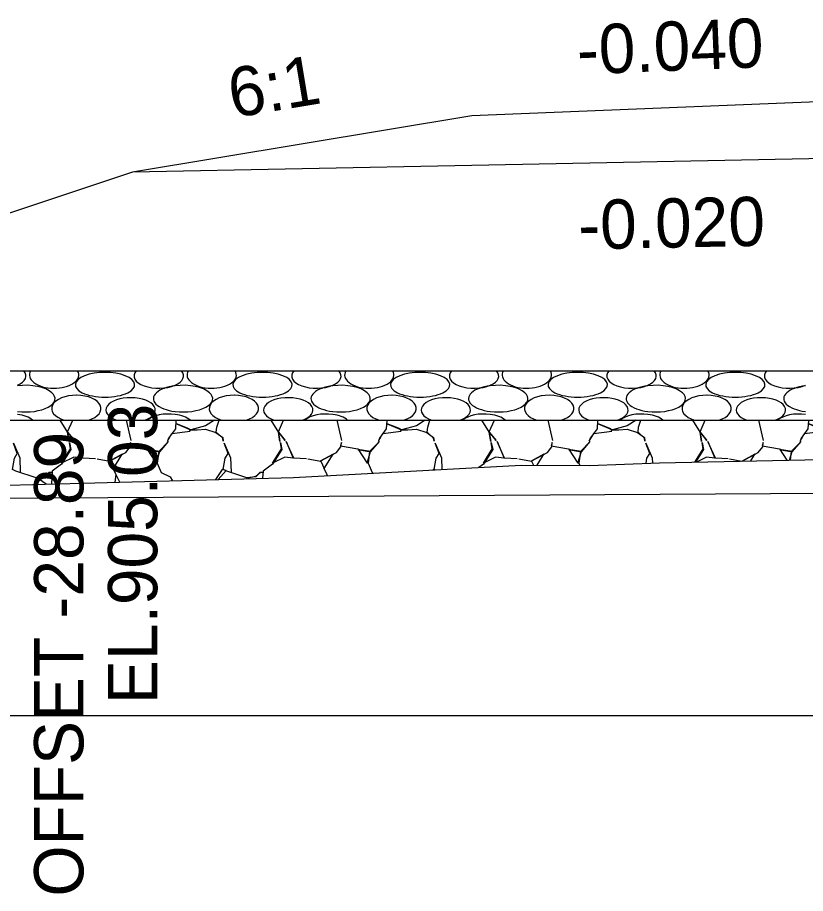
# Model space of a CAD drawing. Extents: x -26 to 4781, y -31 to 24738.
# Drawn here: x 2268.78 to 2284.77, y 13996.39 to 14014.17 of the extents above; entities that cross this region are included whole.
import ezdxf

# ---------------------------------------------------------------- set-up
doc = ezdxf.new("R2010")
doc.units = 0
for name, color, linetype in [('DESIGN - SCRATCH - User 1', 7, 'Continuous'), ('DESIGN - SHEET - Light Grid', 7, 'Continuous'), ('DESIGN - TRANSPORTATION - Proposed Layout Patterning', 7, 'Continuous'), ('DESIGN - TYPICAL - Finished Grade and Subgrade', 7, 'Continuous'), ('DESIGN - TYPICAL - Finished Grade Slopes Text', 7, 'Continuous'), ('DESIGN - TYPICAL - Subgrade Cross Slope Text', 7, 'Continuous'), ('DESIGN - TYPICAL - Subgrade Tie Text', 7, 'Continuous'), ('GEOTECHNICAL – SCRATCH – Level 1', 7, 'Continuous'), ('SURVEY - GROUND - Top of Ground', 7, 'Continuous')]:
    doc.layers.add(name, color=color, linetype=linetype)

msp = doc.modelspace()

# ---------------------------------------------------------------- linework, layer by layer
at = {"layer": 'DESIGN - SCRATCH - User 1'}
for p in [(2365.227, 14005), (2320.053, 14004.723)]:
    msp.add_line(p, (2250.908, 14004.298), dxfattribs=at)
at = {"layer": 'DESIGN - SHEET - Light Grid'}
msp.add_line((2000, 14000), (2300, 14000), dxfattribs=at)
at = {"layer": 'DESIGN - TRANSPORTATION - Proposed Layout Patterning'}
for p, q in [((2271.083, 14005.585), (2270.988, 14006)), ((2275.363, 14005.585), (2275.268, 14006)), ((2279.643, 14005.585), (2279.548, 14006)), ((2283.923, 14005.585), (2283.828, 14005.999)), ((2283.233, 14005.215), (2283.479, 14005.168))]:
    msp.add_line(p, q, dxfattribs=at)
for points in [[(2269.637, 14006), (2269.793, 14005.745), (2269.823, 14005.565), (2269.793, 14005.755), (2269.933, 14005.585), (2269.793, 14005.765), (2269.899, 14006)], [(2271.991, 14006), (2271.993, 14005.995), (2271.983, 14005.825), (2271.843, 14005.635), (2271.823, 14005.575), (2271.913, 14005.725), (2272.283, 14005.775), (2272.263, 14005.825), (2272.003, 14005.925), (2272.293, 14005.805), (2272.423, 14005.805), (2272.593, 14005.815), (2272.803, 14005.745), (2272.943, 14005.645), (2272.953, 14005.575), (2272.943, 14005.635), (2272.813, 14005.755), (2272.823, 14005.855), (2272.869, 14006)], [(2272.773, 14006), (2272.593, 14005.885), (2272.293, 14005.805)], [(2273.917, 14006), (2274.073, 14005.745), (2274.103, 14005.565), (2274.073, 14005.755), (2274.213, 14005.585), (2274.073, 14005.765), (2274.179, 14006)], [(2276.271, 14006), (2276.273, 14005.995), (2276.263, 14005.825), (2276.123, 14005.635), (2276.103, 14005.575), (2276.193, 14005.725), (2276.563, 14005.775), (2276.543, 14005.825), (2276.283, 14005.925), (2276.573, 14005.805), (2276.703, 14005.805), (2276.873, 14005.815), (2277.083, 14005.745), (2277.223, 14005.645), (2277.233, 14005.575), (2277.223, 14005.635), (2277.093, 14005.755), (2277.103, 14005.855), (2277.148, 14006)], [(2277.053, 14006), (2276.873, 14005.885), (2276.573, 14005.805)], [(2278.197, 14006), (2278.353, 14005.745), (2278.383, 14005.565), (2278.353, 14005.755), (2278.493, 14005.585), (2278.353, 14005.765), (2278.459, 14006)], [(2280.551, 14005.999), (2280.553, 14005.995), (2280.543, 14005.825), (2280.403, 14005.635), (2280.383, 14005.575), (2280.473, 14005.725), (2280.843, 14005.775), (2280.823, 14005.825), (2280.563, 14005.925), (2280.853, 14005.805), (2280.983, 14005.805), (2281.153, 14005.815), (2281.363, 14005.745), (2281.503, 14005.645), (2281.513, 14005.575), (2281.503, 14005.635), (2281.373, 14005.755), (2281.383, 14005.855), (2281.428, 14005.999)], [(2281.333, 14005.999), (2281.153, 14005.885), (2280.853, 14005.805)], [(2282.477, 14005.999), (2282.633, 14005.745), (2282.663, 14005.565), (2282.633, 14005.755), (2282.773, 14005.585), (2282.633, 14005.765), (2282.739, 14005.999)], [(2284.831, 14005.999), (2284.833, 14005.995), (2284.823, 14005.825), (2284.683, 14005.635), (2284.663, 14005.575), (2284.753, 14005.725), (2285.123, 14005.775), (2285.103, 14005.825), (2284.843, 14005.925), (2285.133, 14005.805), (2285.263, 14005.805), (2285.433, 14005.815), (2285.643, 14005.745), (2285.783, 14005.645), (2285.793, 14005.575), (2285.783, 14005.635), (2285.653, 14005.755), (2285.663, 14005.855), (2285.708, 14005.999)], [(2270.363, 14005.215), (2270.103, 14005.225), (2269.953, 14005.565), (2270.093, 14005.225), (2269.923, 14005.245), (2269.673, 14005.125), (2269.853, 14005.415), (2269.833, 14005.545), (2269.863, 14005.405), (2269.673, 14005.105), (2269.483, 14004.965), (2269.464, 14004.703)], [(2270.393, 14005.215), (2270.653, 14005.165), (2270.723, 14005.015), (2270.903, 14005.305), (2270.643, 14005.165), (2270.973, 14005.345), (2271.063, 14005.455), (2271.073, 14005.545), (2271.053, 14005.475), (2271.403, 14005.415), (2271.593, 14005.125), (2271.663, 14005.365), (2271.403, 14005.405), (2271.663, 14005.355), (2271.843, 14005.565), (2271.643, 14005.365), (2271.613, 14005.125), (2271.693, 14004.935), (2271.873, 14004.845), (2271.921, 14004.769)], [(2274.643, 14005.215), (2274.383, 14005.225), (2274.233, 14005.565), (2274.373, 14005.225), (2274.203, 14005.245), (2273.953, 14005.125), (2274.133, 14005.415), (2274.113, 14005.545), (2274.143, 14005.405), (2273.953, 14005.105), (2273.763, 14004.965), (2273.752, 14004.818)], [(2274.673, 14005.215), (2274.933, 14005.165), (2275.003, 14005.015), (2275.183, 14005.305), (2274.923, 14005.165), (2275.253, 14005.345), (2275.343, 14005.455), (2275.353, 14005.545), (2275.333, 14005.475), (2275.683, 14005.415), (2275.873, 14005.125), (2275.943, 14005.365), (2275.683, 14005.405), (2275.943, 14005.355), (2276.123, 14005.565), (2275.923, 14005.365), (2275.893, 14005.125), (2275.973, 14004.935), (2276, 14004.922)], [(2278.923, 14005.215), (2278.663, 14005.225), (2278.513, 14005.565), (2278.653, 14005.225), (2278.483, 14005.245), (2278.233, 14005.125), (2278.413, 14005.415), (2278.393, 14005.545), (2278.423, 14005.405), (2278.233, 14005.105), (2278.139, 14005.036)], [(2279.324, 14005.082), (2279.463, 14005.305), (2279.203, 14005.165), (2279.533, 14005.345), (2279.623, 14005.455), (2279.633, 14005.545), (2279.613, 14005.475), (2279.963, 14005.415), (2280.153, 14005.125), (2280.223, 14005.365), (2279.963, 14005.405), (2280.223, 14005.355), (2280.403, 14005.565), (2280.203, 14005.365), (2280.173, 14005.125), (2280.191, 14005.081)], [(2282.527, 14005.148), (2282.693, 14005.415), (2282.673, 14005.545), (2282.703, 14005.405), (2282.54, 14005.148)], [(2283.203, 14005.215), (2282.943, 14005.225), (2282.793, 14005.565), (2282.933, 14005.225), (2282.763, 14005.245), (2282.562, 14005.149)], [(2283.488, 14005.168), (2283.813, 14005.345), (2283.903, 14005.455), (2283.913, 14005.545), (2283.893, 14005.475), (2284.243, 14005.415), (2284.392, 14005.187)], [(2284.451, 14005.188), (2284.503, 14005.365), (2284.243, 14005.405), (2284.503, 14005.355), (2284.683, 14005.565), (2284.483, 14005.365), (2284.46, 14005.188)], [(2269.36, 14004.7), (2269.173, 14004.825), (2269.333, 14004.865), (2269.433, 14004.945), (2269.483, 14004.935), (2269.413, 14004.935), (2269.333, 14004.845), (2269.153, 14004.825), (2268.743, 14004.965), (2268.673, 14004.995), (2268.713, 14005.225), (2268.773, 14005.325), (2268.693, 14005.535), (2268.823, 14005.235), (2268.833, 14004.945)], [(2273.474, 14004.811), (2273.453, 14004.825), (2273.613, 14004.865), (2273.713, 14004.945), (2273.763, 14004.935), (2273.693, 14004.935), (2273.613, 14004.845), (2273.433, 14004.825), (2273.023, 14004.965), (2272.953, 14004.995), (2272.993, 14005.225), (2273.053, 14005.325), (2272.973, 14005.535), (2273.103, 14005.235), (2273.113, 14004.945)], [(2277.248, 14004.988), (2277.233, 14004.995), (2277.273, 14005.225), (2277.333, 14005.325), (2277.253, 14005.535), (2277.383, 14005.235), (2277.391, 14004.996)], [(2281.535, 14005.123), (2281.553, 14005.225), (2281.613, 14005.325), (2281.533, 14005.535), (2281.663, 14005.235), (2281.666, 14005.128)], [(2278.953, 14005.215), (2279.213, 14005.165), (2279.251, 14005.082)], [(2283.66, 14005.172), (2283.743, 14005.305), (2283.488, 14005.168)], [(2270.857, 14004.74), (2270.773, 14004.905), (2270.713, 14005.025), (2270.773, 14004.895), (2270.756, 14004.737)], [(2275.07, 14004.872), (2275.053, 14004.905), (2274.993, 14005.025), (2275.053, 14004.895), (2275.05, 14004.871)], [(2272.852, 14004.794), (2273.013, 14004.975), (2272.933, 14004.995), (2272.795, 14004.792)], [(2277.241, 14004.988), (2277.213, 14004.995), (2277.206, 14004.986)]]:
    msp.add_lwpolyline(points, dxfattribs=at)
for centre, major_axis, ratio, start_param, end_param in [((2268.447, 14006.897), (-0.501, 0), 0.5, 2.292187, 3.5632), ((2269.52, 14006.917), (-0.501, 0), 0.54, 5.973414, 7.825415), ((2269.52, 14006.917), (-0.501, 0), 0.54, 1.545388, 3.451364), ((2270.553, 14006.717), (-0.602, 0), 0.416667, 2.446, 6.978671), ((2271.645, 14006.897), (-0.501, 0), 0.5, 5.861578, 8.575372), ((2271.646, 14006.897), (-0.501, 0), 0.5, 2.292187, 3.5632), ((2272.719, 14006.917), (-0.501, 0), 0.54, 5.973414, 7.825415), ((2272.719, 14006.917), (-0.501, 0), 0.54, 1.545388, 3.451364), ((2273.751, 14006.717), (-0.602, 0), 0.416667, 2.446, 6.978671), ((2274.844, 14006.897), (-0.501, 0), 0.5, 5.861578, 8.575372), ((2274.845, 14006.897), (-0.501, 0), 0.5, 2.292187, 3.5632), ((2275.918, 14006.917), (-0.501, 0), 0.54, 5.973414, 7.825415), ((2275.918, 14006.917), (-0.501, 0), 0.54, 1.545388, 3.451364), ((2276.95, 14006.717), (-0.602, 0), 0.416667, 2.446, 6.978671), ((2278.043, 14006.897), (-0.501, 0), 0.5, 5.861578, 8.575372), ((2278.044, 14006.897), (-0.501, 0), 0.5, 2.292187, 3.5632), ((2279.116, 14006.917), (-0.501, 0), 0.54, 5.973414, 7.825415), ((2279.116, 14006.917), (-0.501, 0), 0.54, 1.545388, 3.451364), ((2280.149, 14006.717), (-0.602, 0), 0.416667, 2.446, 6.978671), ((2281.242, 14006.897), (-0.501, 0), 0.5, 5.861578, 8.575372), ((2281.242, 14006.897), (-0.501, 0), 0.5, 2.292187, 3.5632), ((2282.315, 14006.917), (-0.501, 0), 0.54, 5.973414, 7.825415), ((2282.315, 14006.917), (-0.501, 0), 0.54, 1.545388, 3.451364), ((2283.348, 14006.717), (-0.602, 0), 0.416667, 2.446, 6.978671), ((2284.441, 14006.897), (-0.501, 0), 0.5, 5.861578, 8.575372), ((2268.938, 14006.436), (-0.602, 0), 0.45, 3.602876, 4.982641), ((2272.137, 14006.436), (-0.602, 0), 0.45, 4.982641, 5.821976), ((2272.137, 14006.436), (-0.602, 0), 0.45, 3.602876, 4.982641), ((2275.336, 14006.436), (-0.602, 0), 0.45, 4.982641, 5.821976), ((2275.336, 14006.436), (-0.602, 0), 0.45, 3.602876, 4.982641), ((2278.534, 14006.436), (-0.602, 0), 0.45, 4.982641, 5.821976), ((2278.535, 14006.436), (-0.602, 0), 0.45, 3.602876, 4.982641), ((2281.733, 14006.436), (-0.602, 0), 0.45, 4.982641, 5.821976), ((2281.734, 14006.436), (-0.602, 0), 0.45, 3.602876, 4.982641), ((2284.932, 14006.436), (-0.602, 0), 0.45, 4.982641, 5.821976), ((2268.938, 14006.436), (-0.602, 0), 0.45, 1.300445, 3.602877), ((2269.971, 14006.235), (-0.501, 0), 0.54, 4.698848, 7.338852), ((2269.971, 14006.235), (-0.501, 0), 0.54, 2.08585, 4.691622), ((2270.553, 14006.717), (-0.602, 0), 0.416667, 0.695486, 2.446), ((2271.074, 14006.205), (-0.501, 0), 0.5, 4.691313, 7.244481), ((2271.074, 14006.205), (-0.501, 0), 0.5, 2.180215, 4.683059), ((2272.137, 14006.436), (-0.602, 0), 0.45, 5.821976, 7.58363), ((2272.137, 14006.436), (-0.602, 0), 0.45, 1.300445, 3.602877), ((2273.17, 14006.235), (-0.501, 0), 0.54, 4.698848, 7.339344), ((2273.17, 14006.235), (-0.501, 0), 0.54, 2.085358, 4.691622), ((2273.751, 14006.717), (-0.602, 0), 0.416667, 0.695486, 2.446), ((2274.273, 14006.205), (-0.501, 0), 0.5, 4.691313, 7.244938), ((2274.273, 14006.205), (-0.501, 0), 0.5, 2.179758, 4.683059), ((2275.336, 14006.436), (-0.602, 0), 0.45, 5.821976, 7.58363), ((2275.336, 14006.436), (-0.602, 0), 0.45, 1.300445, 3.602877), ((2276.369, 14006.235), (-0.501, 0), 0.54, 4.698848, 7.339836), ((2276.369, 14006.235), (-0.501, 0), 0.54, 2.084866, 4.691622), ((2276.95, 14006.717), (-0.602, 0), 0.416667, 0.695486, 2.446), ((2277.472, 14006.205), (-0.501, 0), 0.5, 4.691313, 7.245396), ((2277.472, 14006.205), (-0.501, 0), 0.5, 2.1793, 4.683059), ((2278.534, 14006.436), (-0.602, 0), 0.45, 5.821976, 7.58363), ((2278.535, 14006.436), (-0.602, 0), 0.45, 1.300445, 3.602877), ((2279.568, 14006.235), (-0.501, 0), 0.54, 4.698848, 7.340329), ((2279.568, 14006.235), (-0.501, 0), 0.54, 2.084373, 4.691622), ((2280.149, 14006.717), (-0.602, 0), 0.416667, 0.695486, 2.446), ((2280.67, 14006.205), (-0.501, 0), 0.5, 4.691313, 7.245853), ((2280.67, 14006.205), (-0.501, 0), 0.5, 2.178842, 4.683059), ((2281.733, 14006.436), (-0.602, 0), 0.45, 5.821976, 7.58363), ((2281.734, 14006.436), (-0.602, 0), 0.45, 1.300445, 3.602877), ((2282.766, 14006.235), (-0.501, 0), 0.54, 4.698848, 7.340822), ((2282.766, 14006.235), (-0.501, 0), 0.54, 2.08388, 4.691622), ((2283.348, 14006.717), (-0.602, 0), 0.416667, 0.695486, 2.446), ((2283.869, 14006.205), (-0.501, 0), 0.5, 4.691313, 7.246312), ((2283.869, 14006.205), (-0.501, 0), 0.5, 2.178384, 4.683059), ((2284.932, 14006.436), (-0.602, 0), 0.45, 5.821976, 7.58363), ((2268.648, 14005.874), (-0.501, 0), 0.5, 3.665429, 4.449052), ((2271.846, 14005.874), (-0.501, 0), 0.5, 4.449052, 5.759569), ((2271.846, 14005.874), (-0.501, 0), 0.5, 3.665126, 4.449052), ((2275.045, 14005.874), (-0.501, 0), 0.5, 4.449052, 5.759871), ((2275.045, 14005.874), (-0.501, 0), 0.5, 3.664824, 4.449052), ((2278.244, 14005.874), (-0.501, 0), 0.5, 4.449052, 5.760173), ((2278.244, 14005.874), (-0.501, 0), 0.5, 3.664522, 4.449052), ((2281.442, 14005.874), (-0.501, 0), 0.5, 4.449052, 5.760475), ((2281.443, 14005.874), (-0.501, 0), 0.5, 3.664221, 4.449052), ((2284.641, 14005.874), (-0.501, 0), 0.5, 4.449052, 5.760777)]:
    msp.add_ellipse(centre, major_axis=major_axis, ratio=ratio, start_param=start_param, end_param=end_param, dxfattribs=at)
at = {"layer": 'DESIGN - TYPICAL - Finished Grade and Subgrade'}
for p, q in [((2288, 14012.581), (2278, 14012.181)), ((2278, 14012.181), (2271.114, 14011.034)), ((2288, 14011.371), (2278, 14011.171)), ((2278, 14011.171), (2271.114, 14011.034)), ((2271.114, 14011.034), (2250.908, 14004.298))]:
    msp.add_line(p, q, dxfattribs=at)
at = {"layer": 'GEOTECHNICAL – SCRATCH – Level 1'}
for p, q in [((2259.012, 14007), (2316.679, 14007)), ((2256.012, 14006), (2302.961, 14006))]:
    msp.add_line(p, q, dxfattribs=at)
at = {"layer": 'SURVEY - GROUND - Top of Ground'}
msp.add_lwpolyline([(2249.183, 14004.277), (2255.202, 14004.351), (2256.492, 14004.475), (2258.38, 14004.478), (2260.077, 14004.504), (2263.284, 14004.537), (2274.38, 14004.835), (2278.999, 14005.082), (2280.386, 14005.08), (2281.807, 14005.133), (2291.318, 14005.33), (2300, 14005.837), (2302.946, 14005.999), (2306.357, 14006.23), (2316.994, 14007.023), (2322.783, 14007.537), (2327.337, 14008.077), (2330.191, 14008.265), (2331.923, 14008.376), (2332.99, 14008.274), (2334.585, 14009.964), (2340.115, 14012.249)], dxfattribs=at)

# ---------------------------------------------------------------- texts
at = {"layer": 'DESIGN - TYPICAL - Finished Grade Slopes Text'}
for s, rotation, p in [('-0.040', 2.2906, (2280.149, 14013.017)), ('6:1', 9.4623, (2273.145, 14012.133))]:
    msp.add_text(s, height=1, rotation=rotation, dxfattribs=at).set_placement(p)
at = {"layer": 'DESIGN - TYPICAL - Subgrade Cross Slope Text'}
msp.add_text('-0.020', height=1, rotation=1.1458, dxfattribs=at).set_placement((2280.167, 14009.465))
at = {"layer": 'DESIGN - TYPICAL - Subgrade Tie Text'}
for s, p in [('EL.905.03', (2271.614, 14000.236)), ('OFFSET -28.89', (2270.114, 13996.324))]:
    msp.add_text(s, height=1, rotation=90, dxfattribs=at).set_placement(p)

doc.saveas('drawing.dxf')
